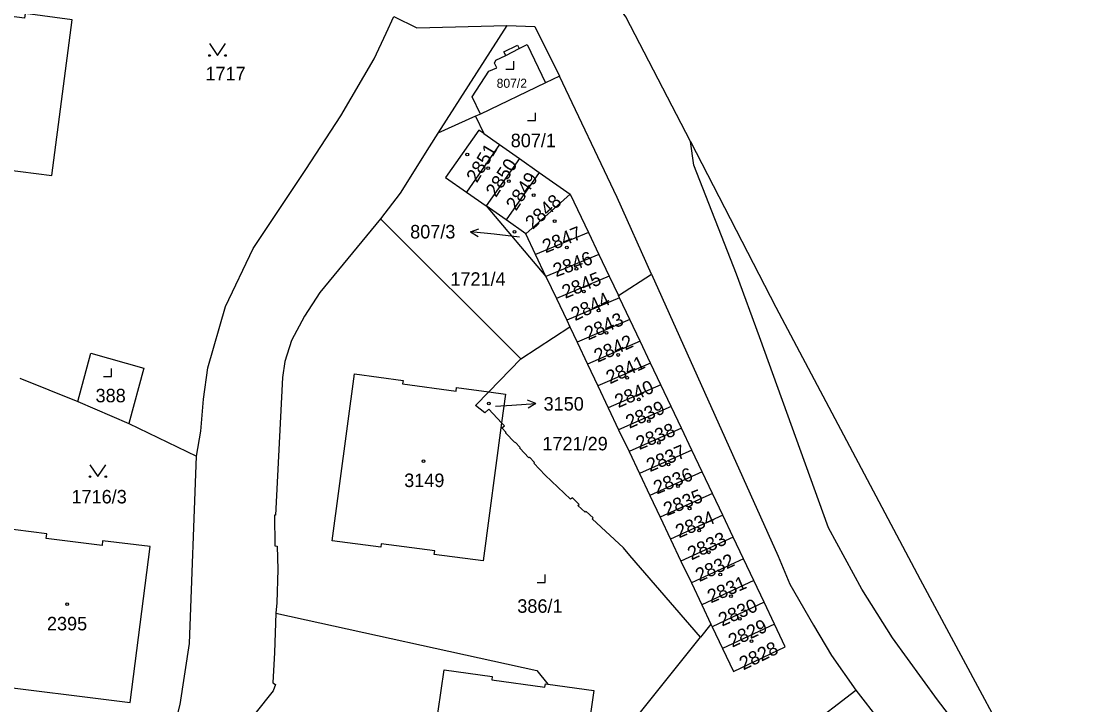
# Model space of a CAD drawing. Extents: x -679220 to -673243, y -1075091 to -1066557.
# Drawn here: x -676777.4 to -676644.6, y -1071830.7 to -1071744.6 of the extents above; entities that cross this region are included whole.
import ezdxf

# ---------------------------------------------------------------- set-up
doc = ezdxf.new("R2010")
doc.units = 0
for name, color, linetype in [('Hranice parcel', 7, 'Continuous'), ('Parcelní čísla', 7, 'Continuous'), ('Pop  PČ popisy', 7, 'Continuous'), ('Vnitřní kresba', 7, 'Continuous'), ('Značky budov', 7, 'Continuous'), ('Značky kultur', 7, 'Continuous')]:
    doc.layers.add(name, color=color, linetype=linetype)

msp = doc.modelspace()

# ---------------------------------------------------------------- linework, layer by layer
at = {"layer": 'Hranice parcel'}
for p, q in [((-676716.3, -1071745.18), (-676724.98, -1071758.74)), ((-676720.25, -1071756.63), (-676724.98, -1071758.74)), ((-676720.25, -1071756.63), (-676719.21, -1071758.81)), ((-676719.21, -1071758.81), (-676717.23, -1071760.2)), ((-676717.23, -1071760.2), (-676721.37, -1071766.18)), ((-676717.23, -1071760.2), (-676714.73, -1071761.95)), ((-676714.73, -1071761.95), (-676718.9, -1071767.92)), ((-676714.73, -1071761.95), (-676712.23, -1071763.7)), ((-676712.23, -1071763.7), (-676716.41, -1071769.68)), ((-676712.23, -1071763.7), (-676708.34, -1071766.42)), ((-676721.37, -1071766.18), (-676718.9, -1071767.92)), ((-676708.34, -1071766.42), (-676713.93, -1071771.42)), ((-676708.34, -1071766.42), (-676706.04, -1071771.27)), ((-676716.41, -1071769.68), (-676718.9, -1071767.92)), ((-676718.9, -1071767.92), (-676711.38, -1071776.8)), ((-676714.55, -1071787.16), (-676732.19, -1071769.55)), ((-676713.93, -1071771.42), (-676716.41, -1071769.68)), ((-676712.69, -1071774.04), (-676713.93, -1071771.42)), ((-676706.04, -1071771.27), (-676712.69, -1071774.04)), ((-676706.04, -1071771.27), (-676704.74, -1071774.01)), ((-676711.38, -1071776.8), (-676712.69, -1071774.04)), ((-676704.74, -1071774.01), (-676711.38, -1071776.8)), ((-676704.74, -1071774.01), (-676703.44, -1071776.74)), ((-676702.27, -1071779.21), (-676698.11, -1071776.51)), ((-676711.38, -1071776.8), (-676710.07, -1071779.55)), ((-676703.44, -1071776.74), (-676710.07, -1071779.55)), ((-676703.44, -1071776.74), (-676702.27, -1071779.21)), ((-676710.07, -1071779.55), (-676708.77, -1071782.31)), ((-676702.14, -1071779.48), (-676708.77, -1071782.31)), ((-676702.14, -1071779.48), (-676702.27, -1071779.21)), ((-676700.84, -1071782.22), (-676702.14, -1071779.48)), ((-676714.55, -1071787.16), (-676708.37, -1071783.15)), ((-676708.77, -1071782.31), (-676708.37, -1071783.15)), ((-676708.37, -1071783.15), (-676707.46, -1071785.06)), ((-676700.84, -1071782.22), (-676707.46, -1071785.06)), ((-676699.54, -1071784.96), (-676700.84, -1071782.22)), ((-676707.46, -1071785.06), (-676706.16, -1071787.82)), ((-676699.54, -1071784.96), (-676706.16, -1071787.82)), ((-676698.24, -1071787.69), (-676699.54, -1071784.96)), ((-676718.59, -1071791.32), (-676714.55, -1071787.16)), ((-676706.16, -1071787.82), (-676704.85, -1071790.58)), ((-676698.24, -1071787.69), (-676704.85, -1071790.58)), ((-676696.94, -1071790.43), (-676698.24, -1071787.69)), ((-676777.6, -1071789.6), (-676770.27, -1071792.52)), ((-676704.85, -1071790.58), (-676703.54, -1071793.33)), ((-676696.94, -1071790.43), (-676703.54, -1071793.33)), ((-676695.64, -1071793.17), (-676696.94, -1071790.43)), ((-676770.27, -1071792.52), (-676763.88, -1071795.29)), ((-676703.54, -1071793.33), (-676702.24, -1071796.09)), ((-676695.64, -1071793.17), (-676702.24, -1071796.09)), ((-676694.34, -1071795.91), (-676695.64, -1071793.17)), ((-676763.88, -1071795.29), (-676755.36, -1071799.42)), ((-676702.24, -1071796.09), (-676700.93, -1071798.84)), ((-676694.34, -1071795.91), (-676700.93, -1071798.84)), ((-676693.04, -1071798.65), (-676694.34, -1071795.91)), ((-676700.93, -1071798.84), (-676699.62, -1071801.6)), ((-676693.04, -1071798.65), (-676699.62, -1071801.6)), ((-676691.74, -1071801.38), (-676693.04, -1071798.65)), ((-676699.62, -1071801.6), (-676698.32, -1071804.36)), ((-676691.74, -1071801.38), (-676698.32, -1071804.36)), ((-676690.44, -1071804.12), (-676691.74, -1071801.38)), ((-676698.32, -1071804.36), (-676697.01, -1071807.11)), ((-676690.44, -1071804.12), (-676697.01, -1071807.11)), ((-676689.14, -1071806.86), (-676690.44, -1071804.12)), ((-676689.14, -1071806.86), (-676695.7, -1071809.87)), ((-676687.84, -1071809.6), (-676689.14, -1071806.86)), ((-676697.01, -1071807.11), (-676695.7, -1071809.87)), ((-676687.84, -1071809.6), (-676694.4, -1071812.62)), ((-676686.54, -1071812.33), (-676687.84, -1071809.6)), ((-676695.7, -1071809.87), (-676694.4, -1071812.62)), ((-676686.54, -1071812.33), (-676693.09, -1071815.38)), ((-676685.24, -1071815.07), (-676686.54, -1071812.33)), ((-676694.4, -1071812.62), (-676693.09, -1071815.38)), ((-676693.09, -1071815.38), (-676691.78, -1071818.14)), ((-676685.24, -1071815.07), (-676691.78, -1071818.14)), ((-676683.94, -1071817.81), (-676685.24, -1071815.07)), ((-676691.78, -1071818.14), (-676690.63, -1071820.57)), ((-676683.94, -1071817.81), (-676690.48, -1071820.89)), ((-676682.64, -1071820.55), (-676683.94, -1071817.81)), ((-676690.63, -1071820.57), (-676691.95, -1071822.2)), ((-676690.63, -1071820.57), (-676690.48, -1071820.89)), ((-676690.48, -1071820.89), (-676689.17, -1071823.65)), ((-676682.64, -1071820.55), (-676689.17, -1071823.65)), ((-676707.13, -1071841.17), (-676691.95, -1071822.2)), ((-676702.61, -1071852.03), (-676672.38, -1071828.88))]:
    msp.add_line(p, q, dxfattribs=at)
for points in [[(-676693.21, -1071759.8), (-676701.32, -1071744.09), (-676717.48, -1071721.4)], [(-676773.55, -1071764.09), (-676771, -1071744.47), (-676776.92, -1071743.7), (-676777, -1071744.29), (-676784.12, -1071743.37), (-676784.04, -1071742.77), (-676789.95, -1071742.01), (-676792.53, -1071761.62), (-676786.59, -1071762.39), (-676786.52, -1071761.79), (-676779.4, -1071762.72), (-676779.47, -1071763.32), (-676773.55, -1071764.09)], [(-676755.36, -1071799.42), (-676754.79, -1071796.28), (-676754.47, -1071792.26), (-676753.92, -1071788.28), (-676751.72, -1071780.58), (-676748.21, -1071773.29), (-676741.58, -1071763.33), (-676737.2, -1071756.59), (-676733.02, -1071749.38), (-676731.47, -1071746.17), (-676730.54, -1071744.07)], [(-676730.54, -1071744.07), (-676727.64, -1071745.5), (-676716.3, -1071745.18)], [(-676716.3, -1071745.18), (-676712.79, -1071745.31), (-676709.69, -1071751.58)], [(-676709.69, -1071751.58), (-676711.43, -1071752.43), (-676719.64, -1071756.35), (-676720.25, -1071756.63)], [(-676698.11, -1071776.51), (-676702.42, -1071766.86), (-676709.69, -1071751.58)], [(-676724.98, -1071758.74), (-676726.07, -1071760.49), (-676729.74, -1071766.29), (-676732.19, -1071769.55)], [(-676719.21, -1071758.81), (-676719.85, -1071758.36), (-676724.01, -1071764.32), (-676721.37, -1071766.18)], [(-676536.59, -1072122.5), (-676533.92, -1072098.22), (-676545.12, -1072067.43), (-676565.16, -1072040.09), (-676600.33, -1072005.09), (-676616.66, -1071979.22), (-676622.81, -1071969.28), (-676636.28, -1071948.34), (-676643.38, -1071915.55), (-676643.27, -1071912.66), (-676641.57, -1071878.93), (-676640.51, -1071869.39), (-676644.08, -1071858.21), (-676648.12, -1071848.64), (-676652.14, -1071843.11), (-676662.12, -1071830.1), (-676667.77, -1071822.29), (-676671.63, -1071816.16), (-676675.84, -1071808.46), (-676684.53, -1071784.41), (-676687.42, -1071776.51), (-676692.78, -1071762.77), (-676693.21, -1071759.8)], [(-676693.21, -1071759.8), (-676682.45, -1071780.64), (-676664.29, -1071814.93), (-676647.47, -1071846.25), (-676640.24, -1071862.09), (-676636.02, -1071877.65), (-676635.05, -1071901.27), (-676635.17, -1071919.29), (-676633.29, -1071941.26), (-676629.86, -1071950.91), (-676620.91, -1071965.54), (-676603.92, -1071990.64), (-676585.08, -1072007.38), (-676570.01, -1072017.31), (-676553.76, -1072031.84)], [(-676732.19, -1071769.55), (-676739.85, -1071778.82), (-676741.77, -1071781.78), (-676743.4, -1071784.84), (-676744.23, -1071787.5), (-676744.54, -1071789.51), (-676745.41, -1071806.85), (-676745.56, -1071806.83), (-676745.48, -1071810.72), (-676745.22, -1071810.74), (-676745.14, -1071813.68), (-676745.24, -1071817.89), (-676745.36, -1071819.18)], [(-676698.11, -1071776.51), (-676682.18, -1071812), (-676680.72, -1071815.55), (-676677.74, -1071820.7), (-676675.45, -1071824.52), (-676672.38, -1071828.88)], [(-676770.27, -1071792.52), (-676768.64, -1071786.45), (-676761.98, -1071788.32), (-676763.88, -1071795.29)], [(-676716.97, -1071795.21), (-676719.3, -1071812.58), (-676725.43, -1071811.78), (-676725.37, -1071811.33), (-676732.1, -1071810.45), (-676732.16, -1071810.89), (-676738.27, -1071810.09), (-676735.46, -1071789.06), (-676729.36, -1071789.88), (-676729.42, -1071790.32), (-676722.68, -1071791.22), (-676722.62, -1071790.78), (-676718.59, -1071791.32)], [(-676716.97, -1071795.21), (-676718.59, -1071793.49), (-676719.08, -1071793.95), (-676720.24, -1071793.02), (-676718.59, -1071791.32)], [(-676718.59, -1071791.32), (-676716.48, -1071791.6), (-676716.97, -1071795.21)], [(-676691.95, -1071822.2), (-676700.84, -1071811.92), (-676701.62, -1071810.96), (-676705.57, -1071807.3), (-676705.46, -1071807.19), (-676706.34, -1071806.37), (-676706.45, -1071806.49), (-676707.37, -1071805.64), (-676707.2, -1071805.5), (-676708.06, -1071804.68), (-676708.28, -1071804.84), (-676711.47, -1071801.81), (-676712.92, -1071800.28), (-676712.84, -1071800.21), (-676713.45, -1071799.54), (-676713.53, -1071799.62), (-676714.69, -1071798.41), (-676714.61, -1071798.33), (-676715.24, -1071797.64), (-676715.32, -1071797.72), (-676716.48, -1071796.5), (-676716.4, -1071796.43), (-676716.94, -1071795.86), (-676716.6, -1071795.6), (-676716.97, -1071795.21)], [(-676766.4, -1071842.71), (-676763.17, -1071840.7), (-676760.15, -1071837.83), (-676758.43, -1071834.69), (-676757.4, -1071830.7), (-676756.23, -1071822.99), (-676755.36, -1071799.42)], [(-676782.58, -1071828.1), (-676763.72, -1071830.45), (-676761.17, -1071810.81), (-676767.16, -1071810.06), (-676767.23, -1071810.66), (-676774.26, -1071809.78), (-676774.19, -1071809.19), (-676780.13, -1071808.45), (-676782.58, -1071828.1)], [(-676745.36, -1071819.18), (-676745.52, -1071824.15), (-676745.73, -1071827.94), (-676745.4, -1071828.18), (-676745.72, -1071828.95), (-676750.3, -1071834.75)], [(-676745.36, -1071819.18), (-676712.55, -1071826.39), (-676711.13, -1071828.12)], [(-676689.17, -1071823.65), (-676687.8, -1071826.54), (-676681.28, -1071823.42), (-676682.64, -1071820.55)], [(-676713.91, -1071849.04), (-676714.44, -1071848.96), (-676714.37, -1071848.52), (-676721.06, -1071847.56), (-676721.12, -1071848), (-676727.21, -1071847.13), (-676724.21, -1071826.3), (-676718.15, -1071827.14), (-676718.21, -1071827.59), (-676711.52, -1071828.52), (-676711.46, -1071828.07), (-676711.13, -1071828.12)], [(-676711.13, -1071828.12), (-676705.37, -1071828.92), (-676707.13, -1071841.17)], [(-676672.38, -1071828.88), (-676669.33, -1071832.84), (-676653.63, -1071852.97)]]:
    msp.add_lwpolyline(points, dxfattribs=at)
at = {"layer": 'Pop  PČ popisy'}
for p, q in [((-676720.88, -1071771.18), (-676719.83, -1071770.78)), ((-676717.89, -1071771.49), (-676720.88, -1071771.18)), ((-676720.88, -1071771.18), (-676719.93, -1071771.78)), ((-676714.7, -1071771.85), (-676717.89, -1071771.49)), ((-676712.68, -1071792.8), (-676713.71, -1071792.37)), ((-676717.73, -1071793.14), (-676715.67, -1071793.01)), ((-676715.67, -1071793.01), (-676712.68, -1071792.8)), ((-676712.68, -1071792.8), (-676713.64, -1071793.37))]:
    msp.add_line(p, q, dxfattribs=at)
at = {"layer": 'Vnitřní kresba'}
for p, q in [((-676716.68, -1071748.51), (-676714.98, -1071747.66)), ((-676716.45, -1071748.96), (-676716.68, -1071748.51)), ((-676716.45, -1071748.96), (-676714.75, -1071748.11)), ((-676714.98, -1071747.66), (-676714.75, -1071748.11)), ((-676714.75, -1071748.11), (-676713.73, -1071747.59)), ((-676713.73, -1071747.59), (-676711.43, -1071752.43)), ((-676717.87, -1071749.96), (-676717.7, -1071749.58)), ((-676717.58, -1071750.52), (-676717.87, -1071749.96)), ((-676717.7, -1071749.58), (-676716.45, -1071748.96)), ((-676720.68, -1071754.19), (-676718.59, -1071750.93)), ((-676718.59, -1071750.93), (-676717.58, -1071750.52)), ((-676719.64, -1071756.35), (-676720.68, -1071754.19))]:
    msp.add_line(p, q, dxfattribs=at)
at = {"layer": 'Značky budov'}
for centre in [(-676721.28, -1071761.45), (-676718.66, -1071763.17), (-676716.05, -1071764.79), (-676712.93, -1071766.57), (-676710.29, -1071769.83), (-676715.34, -1071771.17), (-676708.76, -1071773.16), (-676707.56, -1071775.82), (-676706.63, -1071778.68), (-676704.76, -1071781.08), (-676703.76, -1071783.88), (-676702.3, -1071786.68), (-676701.17, -1071789.54), (-676699.7, -1071792.27), (-676718.56, -1071792.8), (-676698.44, -1071795), (-676697.17, -1071797.73), (-676726.78, -1071800.06), (-676695.97, -1071800.46), (-676694.77, -1071803.19), (-676693.31, -1071805.99), (-676692.11, -1071808.79), (-676690.91, -1071811.52), (-676689.45, -1071814.32), (-676688.11, -1071817.05), (-676771.62, -1071818.04), (-676686.98, -1071819.91), (-676685.52, -1071822.71)]:
    msp.add_circle(centre, 0.175, dxfattribs=at)
at = {"layer": 'Značky kultur'}
for p, q in [((-676715.42, -1071750.68), (-676715.42, -1071749.68)), ((-676716.42, -1071750.68), (-676715.42, -1071750.68)), ((-676712.72, -1071757.18), (-676712.72, -1071756.18)), ((-676713.72, -1071757.18), (-676712.72, -1071757.18)), ((-676766.05, -1071789.39), (-676766.05, -1071788.39)), ((-676767.05, -1071789.39), (-676766.05, -1071789.39)), ((-676711.48, -1071815.33), (-676711.48, -1071814.33)), ((-676712.48, -1071815.33), (-676711.48, -1071815.33))]:
    msp.add_line(p, q, dxfattribs=at)
for points in [[(-676753.71, -1071747.48), (-676752.71, -1071748.98), (-676751.71, -1071747.48)], [(-676768.76, -1071800.5), (-676767.76, -1071802), (-676766.76, -1071800.5)]]:
    msp.add_lwpolyline(points, dxfattribs=at)
for centre in [(-676753.71, -1071748.98), (-676751.71, -1071748.98), (-676768.76, -1071802), (-676766.76, -1071802)]:
    msp.add_circle(centre, 0.1, dxfattribs=at)

# ---------------------------------------------------------------- texts
at = {"layer": 'Parcelní čísla'}
for s, height, p in [('1717', 1.7, (-676754.23, -1071752.1)), ('807/2', 1.14, (-676717.59, -1071753.04)), ('807/1', 1.7, (-676715.82, -1071760.52)), ('807/3', 1.7, (-676728.47, -1071772.01)), ('1721/4', 1.7, (-676723.41, -1071777.97)), ('388', 1.7, (-676768.05, -1071792.64)), ('3150', 1.7, (-676711.68, -1071793.68)), ('1721/29', 1.7, (-676711.83, -1071798.69)), ('3149', 1.7, (-676729.22, -1071803.31)), ('1716/3', 1.7, (-676771.08, -1071805.37)), ('386/1', 1.7, (-676714.99, -1071819.14)), ('2395', 1.7, (-676774.17, -1071821.35))]:
    msp.add_text(s, height=height, dxfattribs=at).set_placement(p)
for s, rotation, p in [('2851', 59, (-676720.07, -1071765.09)), ('2850', 57, (-676717.67, -1071766.92)), ('2849', 56, (-676715.15, -1071768.62)), ('2848', 42, (-676713.05, -1071770.94)), ('2847', 22, (-676711.42, -1071773.88)), ('2846', 20, (-676710.12, -1071776.89)), ('2845', 22, (-676708.96, -1071779.61)), ('2844', 26, (-676707.71, -1071782.44)), ('2843', 24, (-676706.07, -1071784.86)), ('2842', 24, (-676704.87, -1071787.66)), ('2841', 25, (-676703.33, -1071790.38)), ('2840', 24, (-676702.27, -1071793.38)), ('2839', 24, (-676700.88, -1071795.98)), ('2838', 22, (-676699.64, -1071798.65)), ('2837', 23, (-676698.3, -1071801.44)), ('2836', 22, (-676697.44, -1071804.25)), ('2835', 22, (-676696.18, -1071806.98)), ('2834', 23, (-676694.64, -1071809.77)), ('2833', 25, (-676693.08, -1071812.55)), ('2832', 25, (-676692.08, -1071815.28)), ('2831', 23, (-676690.64, -1071817.96)), ('2830', 24, (-676689.22, -1071820.89)), ('2829', 25, (-676687.95, -1071823.54)), ('2828', 26, (-676686.54, -1071826.4))]:
    msp.add_text(s, height=1.7, rotation=rotation, dxfattribs=at).set_placement(p)

doc.saveas('drawing.dxf')
